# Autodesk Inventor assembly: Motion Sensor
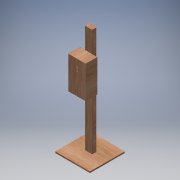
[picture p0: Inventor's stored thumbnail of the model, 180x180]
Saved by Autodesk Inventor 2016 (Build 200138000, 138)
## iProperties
Created: 2018-01
Part Number: Motion Sensor
Document SubType Name: Assembly
Designer: Student
Author: Student
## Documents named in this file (2)
- C:\Users\Student\Desktop\Motion Sensor.iam
- C:\Users\Student\Desktop\Post.ipt
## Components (1 placed, 1 different names)
1. Post:1
